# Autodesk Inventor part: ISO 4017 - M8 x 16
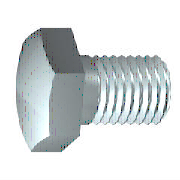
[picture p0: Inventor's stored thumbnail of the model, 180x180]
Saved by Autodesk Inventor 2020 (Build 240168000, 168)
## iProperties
Created: 2011-02
Part Number: ISO 4017 - M8 x 16
Material: Steel, Mild
Document SubType Name: Modeling
Standard: DIN EN 24 017
Designer: lutzd
Standards Organization: DIN
Language: en-US
Size Designation: M8 x 16
Categories: <MemberInstance><Categories><Category DisplayName="Fasteners" InternalName="e4da775c-781d-43d5-af7c-5136215cf5a6" Mnemonic="FSTN"><Category DisplayName="Bolts"
Mass: 12.1561 g
Surface Area: 9.09508 cm^2
Volume: 1.54658 cm^3
Density: 7.86 g/cm^3
Appearance: Stahl
IsCustomPart: 0
Author: lutzd
Title: Sechskantschraube
Revision Number: C
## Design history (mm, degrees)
sketch "Sketch1"
  geometry: L1 (0, 5.815)-(0, 4); L2 (4, 4)-(16, 4); L3 (16, 4)-(16, 0); L4 (16, 0)-(-0.6, 0); L5 (-3.92, 0)-(19.32, 0) reference; L6 (-0.6, 0)-(-0.6, 5.815); L7 (-0.6, 5.815)-(0, 5.815); L8 (4, 4)-(3.233, 4); L9 (3.233, 4)-(0, 4); L10 (0, -1.163)-(0, 6.978) reference
  constraints: 16 end point, 2 collinear, 2 perpendicular, 1 parallel
  dimensions: "d0" = 16 distance between parallel lines of L3 L1 (= NLG); "d1" = 12 distance from line of L2.start L3 (= GEL); "d2" = 8 diameter of L2 L4 (= GD); "d9" = 0.6001 distance between parallel lines of L6 L1 (computed from SD); "d10" = 11.63 diameter of L7 L4 (= SD2); "d13" = 0.76691 distance of L2.start L8.end (computed from GAL); "d14" = 8 diameter of L9 L4 (= BDM)
revolve "Body" sketch "Sketch1" stored, may be unused: angle "d12" = 90 deg
sketch "Sketch2"
  geometry: L1 (0, 7.506)-(6.5, 3.753); L2 (6.5, 3.753)-(6.5, -3.753); L3 (6.5, -3.753)-(0, -7.506); L4 (0, -7.506)-(-6.5, -3.753); L5 (-6.5, -3.753)-(-6.5, 3.753); L6 (-6.5, 3.753)-(0, 7.506); 2 further points
  constraints: 12 end point, 1 coincident, 1 vertical, 11 other
  dimensions: "d11" = 13 distance between parallel lines of L5 L2 (= SW)
extrude "Head" join sketch "Sketch2" distance "d3" = 4.7 (= KOH - SD); taper "d4" = 0 deg
sketch "Sketch4"
  geometry: L1 (-5.3, 6.5)-(-5.3, 7.506); L2 (-5.3, 7.506)-(-4.72, 7.506); L3 (-4.72, 7.506)-(-5.3, 6.5); L4 (-6.24, 0)-(0.34, 0) reference; L5 (-0.6, 7.506)-(-5.3, 7.506) reference; L6 (-5.3, 3.753)-(-5.3, 7.506) reference
  constraints: 6 end point, 2 collinear, 1 perpendicular, 1 vertical
  dimensions: "d5" = 30 deg angle of L3 L1 (= ANG1); "d19" = 13 diameter of L1.start L4 (= SW0)
revolve "Chamfer1" stored, may be unused: angle "d21" = 90 deg
chamfer "Chamfer2" distance "d6" = 0.76681 (= -0.5 x SPD + 0.5 x GD); stored, may be unused: second distance "d7" = 0.76691 (computed from GUL), angle "d55" = 45 deg
feature "Thread" dims "d15" = 12 (= GEL), "d16" = 0
workplane "Work Plane1"
body "Solid1"
other parameters: "NLG" = 16 [user parameter; used in 1 equation term], "GD" = 8 (= NND) [user parameter; used in 2 equation terms], "BDM" = 8 (= NND) [user parameter; used in 1 equation term], "KOH" = 5.3 [user parameter; used in 1 equation term], "GEL" = 12 [user parameter; used in 2 equation terms], "SW" = 13 [user parameter; used in 2 equation terms], "SW0" = 13 (= SW) [user parameter; used in 1 equation term], "SPD" = 6.46637 (= NND - 1.2269 x PTC) [user parameter; used in 1 equation term], "SD2" = 11.63 [user parameter; used in 2 equation terms], "SD" = 0.6 [user parameter; used in 2 equation terms], "ANG1" = 30 deg [user parameter; used in 1 equation term], "GAL" = 0.76681 (= 0.61345 x PTC) [user parameter; used in 1 equation term], "GUL" = 0.76681 (= 0.61345 x PTC) [user parameter; used in 1 equation term], "d8" = 0, "RR" = 0.4 [user parameter], "d57" = 0, "d58" = 0, "TPU" = 8 (computed from PTC) [user parameter], "GD1" = 6.46637 (= THREADDIA - 1.2269 x PTC) [user parameter], "THREADDIA" = 8 [user parameter; used in 1 equation term], "SDH" = 11.63 (= SD2) [user parameter], "SDHG" = 4 [user parameter], "TOA" = 30 deg [user parameter], "PTC" = 1.25 [user parameter; used in 5 equation terms], "NND" = 8 [user parameter; used in 3 equation terms], "E0" = 15.015 [user parameter]
